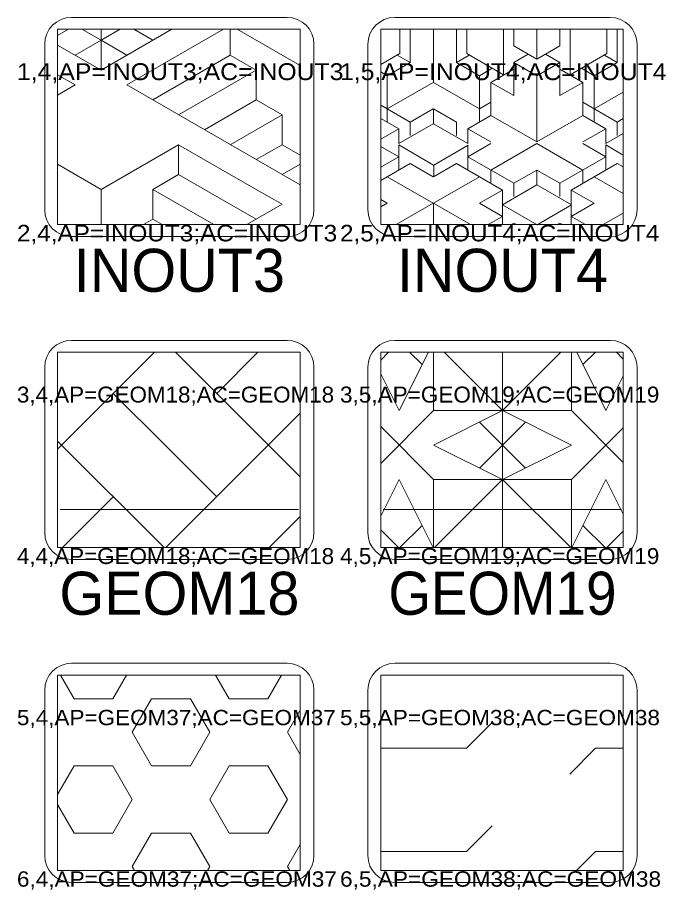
# Model space of a CAD drawing. Extents: x 95935 to 95946.4, y 95971.2 to 95974.7.
# Drawn here: x 95936.835 to 95938.031, y 95973.111 to 95974.732 of the extents above; entities that cross this region are included whole.
import ezdxf
from ezdxf.enums import TextEntityAlignment as Align

# ---------------------------------------------------------------- set-up
doc = ezdxf.new("R2010")
doc.units = 0
doc.header["$LTSCALE"] = 0.032
for name, color, linetype, lineweight in [('1', 7, 'Continuous', 13), ('2', 7, 'Continuous', 13), ('25', 7, 'Continuous', 13), ('6', 7, 'Continuous', 13), ('63', 7, 'Continuous', 13)]:
    doc.layers.add(name, color=color, linetype=linetype, lineweight=lineweight)
doc.layers.add('20', color=7, linetype='Continuous')

msp = doc.modelspace()

# ---------------------------------------------------------------- linework, layer by layer
at = {"layer": '1'}
for p, q in [((95936.9357, 95974.7318), (95937.3357, 95974.7318)), ((95937.5357, 95974.7318), (95937.9357, 95974.7318)), ((95936.8857, 95974.3747), (95936.8857, 95974.6818)), ((95937.3857, 95974.6818), (95937.3857, 95974.3747)), ((95937.4857, 95974.3747), (95937.4857, 95974.6818)), ((95937.9857, 95974.6818), (95937.9857, 95974.3747)), ((95937.3357, 95974.3247), (95936.9357, 95974.3247)), ((95937.9357, 95974.3247), (95937.5357, 95974.3247)), ((95936.9357, 95974.1318), (95937.3357, 95974.1318)), ((95937.5357, 95974.1318), (95937.9357, 95974.1318)), ((95936.8857, 95973.7747), (95936.8857, 95974.0818)), ((95937.3857, 95974.0818), (95937.3857, 95973.7747)), ((95937.4857, 95973.7747), (95937.4857, 95974.0818)), ((95937.9857, 95974.0818), (95937.9857, 95973.7747)), ((95937.3357, 95973.7247), (95936.9357, 95973.7247)), ((95937.9357, 95973.7247), (95937.5357, 95973.7247)), ((95936.9357, 95973.5318), (95937.3357, 95973.5318)), ((95937.5357, 95973.5318), (95937.9357, 95973.5318)), ((95936.8857, 95973.1747), (95936.8857, 95973.4818)), ((95937.3857, 95973.4818), (95937.3857, 95973.1747)), ((95937.4857, 95973.1747), (95937.4857, 95973.4818)), ((95937.9857, 95973.4818), (95937.9857, 95973.1747)), ((95937.3357, 95973.1247), (95936.9357, 95973.1247)), ((95937.9357, 95973.1247), (95937.5357, 95973.1247))]:
    msp.add_line(p, q, dxfattribs=at)
for centre, start, end in [((95936.9357, 95974.6818), 90, 180), ((95937.3357, 95974.6818), 0, 90), ((95937.5357, 95974.6818), 90, 180), ((95937.9357, 95974.6818), 0, 90), ((95936.9357, 95974.3747), 180, 270), ((95937.3357, 95974.3747), 270, 0), ((95937.5357, 95974.3747), 180, 270), ((95937.9357, 95974.3747), 270, 0), ((95936.9357, 95974.0818), 90, 180), ((95937.3357, 95974.0818), 0, 90), ((95937.5357, 95974.0818), 90, 180), ((95937.9357, 95974.0818), 0, 90), ((95936.9357, 95973.7747), 180, 270), ((95937.3357, 95973.7747), 270, 0), ((95937.5357, 95973.7747), 180, 270), ((95937.9357, 95973.7747), 270, 0), ((95936.9357, 95973.4818), 90, 180), ((95937.3357, 95973.4818), 0, 90), ((95937.5357, 95973.4818), 90, 180), ((95937.9357, 95973.4818), 0, 90), ((95936.9357, 95973.1747), 180, 270), ((95937.3357, 95973.1747), 270, 0), ((95937.5357, 95973.1747), 180, 270), ((95937.9357, 95973.1747), 270, 0)]:
    msp.add_arc(centre, 0.05, start, end, dxfattribs=at)
at = {"layer": '2'}
for points in [[(95937.3601, 95974.7099), (95936.9097, 95974.7099), (95936.9097, 95974.3468), (95937.3601, 95974.3468)], [(95937.9601, 95974.7099), (95937.5097, 95974.7099), (95937.5097, 95974.3468), (95937.9601, 95974.3468)], [(95937.3601, 95974.1099), (95936.9097, 95974.1099), (95936.9097, 95973.7468), (95937.3601, 95973.7468)], [(95937.9601, 95974.1099), (95937.5097, 95974.1099), (95937.5097, 95973.7468), (95937.9601, 95973.7468)], [(95937.3601, 95973.5099), (95936.9097, 95973.5099), (95936.9097, 95973.1468), (95937.3601, 95973.1468)], [(95937.9601, 95973.5099), (95937.5097, 95973.5099), (95937.5097, 95973.1468), (95937.9601, 95973.1468)]]:
    msp.add_lwpolyline(points, close=True, dxfattribs=at)
at = {"layer": '25'}
for p, q in [((95937.3569, 95973.8178), (95936.9141, 95973.8178)), ((95937.9569, 95973.8178), (95937.5141, 95973.8178))]:
    msp.add_line(p, q, dxfattribs=at)
at = {"layer": '6'}
for p, q in [((95936.9097, 95974.6982), (95936.9299, 95974.7099)), ((95936.9549, 95974.7099), (95936.9904, 95974.6894)), ((95936.9904, 95974.634), (95937.1219, 95974.7099)), ((95936.9904, 95974.6894), (95937.0259, 95974.7099)), ((95936.9904, 95974.634), (95936.9904, 95974.7099)), ((95937.0384, 95974.6063), (95937.2179, 95974.7099)), ((95937.0509, 95974.7099), (95937.0864, 95974.6894)), ((95937.2304, 95974.6617), (95937.2304, 95974.7099)), ((95937.2429, 95974.7099), (95937.3601, 95974.6423)), ((95937.5453, 95974.6647), (95937.5453, 95974.7099)), ((95937.5644, 95974.6482), (95937.5644, 95974.7098)), ((95937.6076, 95974.6112), (95937.6076, 95974.7099)), ((95937.6503, 95974.6482), (95937.6503, 95974.7098)), ((95937.6694, 95974.6647), (95937.6694, 95974.7099)), ((95937.7379, 95974.6252), (95937.7379, 95974.7099)), ((95937.757, 95974.7099), (95937.757, 95974.679)), ((95937.7996, 95974.7099), (95937.7996, 95974.6544)), ((95937.8423, 95974.7099), (95937.8423, 95974.679)), ((95937.8614, 95974.6252), (95937.8614, 95974.7099)), ((95937.9298, 95974.6647), (95937.9298, 95974.7099)), ((95937.9489, 95974.6482), (95937.9489, 95974.7098)), ((95936.9424, 95974.6617), (95936.9904, 95974.6894)), ((95936.9904, 95974.6894), (95937.0384, 95974.6617)), ((95936.9097, 95974.6806), (95936.9904, 95974.634)), ((95937.7996, 95974.6544), (95937.757, 95974.679)), ((95937.7996, 95974.6544), (95937.8423, 95974.679)), ((95937.0864, 95974.5786), (95937.2304, 95974.6617)), ((95937.2784, 95974.634), (95937.2304, 95974.6617)), ((95937.5097, 95974.6442), (95937.5453, 95974.6647)), ((95937.5644, 95974.6482), (95937.5405, 95974.662)), ((95937.6503, 95974.6482), (95937.6742, 95974.662)), ((95937.7379, 95974.6252), (95937.6694, 95974.6647)), ((95937.757, 95974.6482), (95937.7836, 95974.6636)), ((95937.8423, 95974.6482), (95937.8156, 95974.6636)), ((95937.8614, 95974.6252), (95937.9298, 95974.6647)), ((95937.9489, 95974.6482), (95937.9251, 95974.662)), ((95937.1344, 95974.5509), (95937.2784, 95974.634)), ((95937.5644, 95974.6482), (95937.5217, 95974.6236)), ((95937.6503, 95974.6482), (95937.693, 95974.6236)), ((95937.693, 95974.6236), (95937.7168, 95974.6373)), ((95937.7143, 95974.6112), (95937.757, 95974.6359)), ((95937.757, 95974.5866), (95937.757, 95974.6482)), ((95937.7996, 95974.6236), (95937.757, 95974.6482)), ((95937.7996, 95974.6236), (95937.8423, 95974.6482)), ((95937.8423, 95974.5866), (95937.8423, 95974.6482)), ((95937.8849, 95974.6112), (95937.8423, 95974.6359)), ((95937.9063, 95974.6236), (95937.8824, 95974.6373)), ((95937.9489, 95974.6482), (95937.9063, 95974.6236)), ((95936.9097, 95974.6252), (95936.9424, 95974.6063)), ((95937.5217, 95974.6236), (95937.5097, 95974.6305)), ((95937.5217, 95974.562), (95937.5217, 95974.6236)), ((95937.693, 95974.562), (95937.693, 95974.6236)), ((95937.7996, 95974.5004), (95937.7996, 95974.6236)), ((95937.9063, 95974.562), (95937.9063, 95974.6236)), ((95936.9097, 95974.5874), (95936.9424, 95974.6063)), ((95937.0384, 95974.6063), (95937.3601, 95974.4206)), ((95937.6071, 95974.6112), (95937.5217, 95974.562)), ((95937.6076, 95974.6112), (95937.693, 95974.562)), ((95937.7143, 95974.5497), (95937.7143, 95974.6112)), ((95937.757, 95974.5866), (95937.7143, 95974.6112)), ((95937.8423, 95974.5866), (95937.8849, 95974.6112)), ((95937.8849, 95974.5497), (95937.8849, 95974.6112)), ((95937.9601, 95974.593), (95937.9063, 95974.562)), ((95937.1824, 95974.5232), (95937.2784, 95974.5786)), ((95937.5097, 95974.5689), (95937.5644, 95974.5373)), ((95937.693, 95974.562), (95937.7143, 95974.5743)), ((95937.8849, 95974.5743), (95937.9489, 95974.5373)), ((95937.5217, 95974.562), (95937.5217, 95974.5373)), ((95937.5644, 95974.5373), (95937.6071, 95974.562)), ((95937.6076, 95974.562), (95937.6503, 95974.5374)), ((95937.6076, 95974.562), (95937.6076, 95974.5344)), ((95937.693, 95974.562), (95937.693, 95974.5374)), ((95937.9063, 95974.562), (95937.9063, 95974.5373)), ((95937.2304, 95974.4954), (95937.3264, 95974.5509)), ((95937.3264, 95974.4954), (95937.3264, 95974.5509)), ((95937.5097, 95974.5443), (95937.5431, 95974.525)), ((95937.5644, 95974.5373), (95937.5644, 95974.5127)), ((95937.6503, 95974.5374), (95937.6503, 95974.5127)), ((95937.6716, 95974.525), (95937.7143, 95974.5497)), ((95937.7996, 95974.5004), (95937.7143, 95974.5497)), ((95937.7996, 95974.5004), (95937.8849, 95974.5497)), ((95937.885, 95974.5497), (95937.9276, 95974.525)), ((95937.9489, 95974.5373), (95937.9601, 95974.5438)), ((95937.9489, 95974.5373), (95937.9489, 95974.5127)), ((95937.5097, 95974.5058), (95937.5431, 95974.525)), ((95937.5431, 95974.525), (95937.5431, 95974.4976)), ((95937.5434, 95974.4976), (95937.6071, 95974.5344)), ((95937.6076, 95974.5344), (95937.6716, 95974.4975)), ((95937.6716, 95974.525), (95937.7143, 95974.5004)), ((95937.6716, 95974.525), (95937.6716, 95974.4975)), ((95937.8849, 95974.5004), (95937.9276, 95974.525)), ((95937.9276, 95974.525), (95937.9276, 95974.4976)), ((95937.9279, 95974.4976), (95937.9601, 95974.5162)), ((95936.9904, 95974.4123), (95937.1344, 95974.4954)), ((95937.1344, 95974.4954), (95937.2784, 95974.4123)), ((95937.1344, 95974.44), (95937.1344, 95974.4954)), ((95937.2784, 95974.4677), (95937.3264, 95974.4954)), ((95937.3264, 95974.4954), (95937.3601, 95974.476)), ((95937.5097, 95974.492), (95937.5431, 95974.4728)), ((95937.5431, 95974.4949), (95937.6076, 95974.4576)), ((95937.5431, 95974.4482), (95937.5431, 95974.4949)), ((95937.6082, 95974.4576), (95937.6719, 95974.4944)), ((95937.6716, 95974.4728), (95937.7143, 95974.4975)), ((95937.6716, 95974.4482), (95937.6716, 95974.4944)), ((95937.7143, 95974.4482), (95937.7996, 95974.4975)), ((95937.7996, 95974.4975), (95937.8849, 95974.4482)), ((95937.8849, 95974.4974), (95937.9276, 95974.4728)), ((95937.9276, 95974.4482), (95937.9276, 95974.4949)), ((95937.9276, 95974.4949), (95937.9601, 95974.4761)), ((95937.5097, 95974.4536), (95937.5431, 95974.4728)), ((95937.6716, 95974.4728), (95937.7569, 95974.4236)), ((95937.6716, 95974.4728), (95937.6716, 95974.4482)), ((95937.8423, 95974.4236), (95937.9276, 95974.4728)), ((95936.9097, 95974.4589), (95936.9904, 95974.4123)), ((95937.3264, 95974.44), (95937.3601, 95974.4594)), ((95937.5097, 95974.4289), (95937.5644, 95974.4605)), ((95937.5644, 95974.4605), (95937.6071, 95974.4359)), ((95937.6076, 95974.4359), (95937.6503, 95974.4605)), ((95937.6082, 95974.4576), (95937.6082, 95974.4362)), ((95937.6503, 95974.4605), (95937.7356, 95974.4112)), ((95937.8636, 95974.4112), (95937.9489, 95974.4605)), ((95937.9489, 95974.4605), (95937.9601, 95974.454)), ((95937.0864, 95974.4123), (95937.1344, 95974.44)), ((95937.1344, 95974.44), (95937.1824, 95974.4123)), ((95937.7143, 95974.4482), (95937.7143, 95974.4236)), ((95937.7996, 95974.4482), (95937.7996, 95974.4206)), ((95937.8849, 95974.4482), (95937.8849, 95974.4236)), ((95937.6071, 95974.3866), (95937.5217, 95974.4359)), ((95937.6076, 95974.3866), (95937.693, 95974.4359)), ((95937.7569, 95974.4236), (95937.7569, 95974.3989)), ((95937.8423, 95974.4236), (95937.8423, 95974.3989)), ((95937.9601, 95974.4048), (95937.9063, 95974.4359)), ((95936.9904, 95974.3468), (95936.9904, 95974.4123)), ((95937.0864, 95974.3569), (95937.0864, 95974.4123)), ((95937.0864, 95974.4123), (95937.1999, 95974.3468)), ((95937.1824, 95974.4123), (95937.2784, 95974.3569)), ((95937.2784, 95974.4123), (95937.3264, 95974.3846)), ((95937.693, 95974.3866), (95937.7356, 95974.4112)), ((95937.7356, 95974.4112), (95937.7356, 95974.3468)), ((95937.7359, 95974.3838), (95937.7996, 95974.4206)), ((95937.7996, 95974.4206), (95937.8639, 95974.3835)), ((95937.8636, 95974.4112), (95937.9063, 95974.3866)), ((95937.8636, 95974.4112), (95937.8636, 95974.3468)), ((95937.5097, 95974.3935), (95937.5217, 95974.3866)), ((95937.2609, 95974.3468), (95937.3264, 95974.3846)), ((95937.5097, 95974.3797), (95937.5217, 95974.3866)), ((95937.6071, 95974.3866), (95937.5382, 95974.3468)), ((95937.6076, 95974.3866), (95937.6765, 95974.3468)), ((95937.6076, 95974.3866), (95937.6076, 95974.3468)), ((95937.693, 95974.3866), (95937.7356, 95974.362)), ((95937.7359, 95974.3838), (95937.8002, 95974.3467)), ((95937.8002, 95974.3467), (95937.8639, 95974.3835)), ((95937.8636, 95974.362), (95937.9063, 95974.3866)), ((95937.7094, 95974.3468), (95937.7356, 95974.362)), ((95937.8636, 95974.362), (95937.8899, 95974.3468)), ((95937.8636, 95974.362), (95937.8636, 95974.3468)), ((95937.9601, 95974.3684), (95937.9227, 95974.3468)), ((95936.9119, 95974.3468), (95936.9097, 95974.3481)), ((95937.0689, 95974.3468), (95937.0864, 95974.3569)), ((95937.0864, 95974.3569), (95937.1039, 95974.3468)), ((95937.7519, 95974.3468), (95937.7569, 95974.3497)), ((95937.7569, 95974.3497), (95937.7619, 95974.3468)), ((95937.8373, 95974.3468), (95937.8423, 95974.3497)), ((95937.8423, 95974.3497), (95937.8473, 95974.3468)), ((95937.0896, 95974.1099), (95936.9097, 95973.93)), ((95937.1286, 95974.1099), (95937.3601, 95973.8784)), ((95937.2816, 95974.1099), (95937.2051, 95974.0334)), ((95937.5244, 95974.1099), (95937.5097, 95974.0952)), ((95937.5634, 95974.1099), (95937.5866, 95974.0867)), ((95937.6079, 95974.1099), (95937.6079, 95974.0014)), ((95937.7359, 95974.0014), (95937.6274, 95974.1099)), ((95937.7359, 95974.1099), (95937.7359, 95973.7468)), ((95937.7359, 95974.0014), (95937.8444, 95974.1099)), ((95937.8639, 95974.1099), (95937.8639, 95974.0014)), ((95937.9084, 95974.1099), (95937.8852, 95974.0867)), ((95937.9474, 95974.1099), (95937.9601, 95974.0972)), ((95937.1091, 95973.9374), (95937.0131, 95974.0334)), ((95937.5097, 95973.9032), (95937.6079, 95974.0014)), ((95937.6079, 95974.0014), (95937.7359, 95974.0014)), ((95937.8639, 95974.0014), (95937.7359, 95974.0014)), ((95937.8639, 95974.0014), (95937.9601, 95973.9052)), ((95937.3601, 95973.9964), (95937.1105, 95973.7468)), ((95937.5097, 95973.9716), (95937.6079, 95973.8734)), ((95937.7359, 95973.9374), (95937.6932, 95973.9801)), ((95937.7359, 95973.9374), (95937.7786, 95973.9801)), ((95937.8639, 95973.8734), (95937.9601, 95973.9696)), ((95936.9097, 95973.9448), (95937.1077, 95973.7468)), ((95937.1091, 95973.9374), (95937.2051, 95973.8414)), ((95937.7359, 95973.9374), (95937.6932, 95973.8947)), ((95937.7359, 95973.9374), (95937.7786, 95973.8947)), ((95937.6079, 95973.8734), (95937.7359, 95973.8734)), ((95937.6079, 95973.7468), (95937.6079, 95973.8734)), ((95937.7359, 95973.8734), (95937.6093, 95973.7468)), ((95937.7359, 95973.8734), (95937.8625, 95973.7468)), ((95937.8639, 95973.7468), (95937.8639, 95973.8734)), ((95936.9185, 95973.7468), (95937.0131, 95973.8414)), ((95937.3025, 95973.7468), (95937.3601, 95973.8044)), ((95937.5425, 95973.7468), (95937.5097, 95973.7796)), ((95937.5453, 95973.7468), (95937.5866, 95973.7881)), ((95937.9265, 95973.7468), (95937.8852, 95973.7881)), ((95937.9293, 95973.7468), (95937.9601, 95973.7776)), ((95936.9403, 95973.466), (95936.9149, 95973.5099)), ((95937.0377, 95973.5099), (95937.0123, 95973.466)), ((95937.2283, 95973.466), (95937.2029, 95973.5099)), ((95937.3257, 95973.5099), (95937.3003, 95973.466)), ((95936.9403, 95973.466), (95937.0123, 95973.466)), ((95937.0843, 95973.466), (95937.0483, 95973.4036)), ((95937.0843, 95973.466), (95937.1563, 95973.466)), ((95937.1923, 95973.4036), (95937.1563, 95973.466)), ((95937.2283, 95973.466), (95937.3003, 95973.466)), ((95937.3601, 95973.4449), (95937.3363, 95973.4036)), ((95937.6688, 95973.3741), (95937.7168, 95973.4221)), ((95937.0843, 95973.3413), (95937.0483, 95973.4036)), ((95937.1923, 95973.4036), (95937.1563, 95973.3413)), ((95937.3601, 95973.3624), (95937.3363, 95973.4036)), ((95937.5097, 95973.3741), (95937.6688, 95973.3741)), ((95937.8608, 95973.3261), (95937.9088, 95973.3741)), ((95937.9088, 95973.3741), (95937.9601, 95973.3741)), ((95936.9403, 95973.3413), (95936.9097, 95973.2883)), ((95936.9403, 95973.3413), (95937.0123, 95973.3413)), ((95937.0483, 95973.2789), (95937.0123, 95973.3413)), ((95937.0843, 95973.3413), (95937.1563, 95973.3413)), ((95937.2283, 95973.3413), (95937.1923, 95973.2789)), ((95937.2283, 95973.3413), (95937.3003, 95973.3413)), ((95937.3363, 95973.2789), (95937.3003, 95973.3413)), ((95937.0483, 95973.2789), (95937.0123, 95973.2165)), ((95937.2283, 95973.2165), (95937.1923, 95973.2789)), ((95937.3363, 95973.2789), (95937.3003, 95973.2165)), ((95936.9403, 95973.2165), (95936.9097, 95973.2695)), ((95937.6688, 95973.1821), (95937.7168, 95973.2301)), ((95936.9403, 95973.2165), (95937.0123, 95973.2165)), ((95937.0843, 95973.2165), (95937.0483, 95973.1542)), ((95937.0843, 95973.2165), (95937.1563, 95973.2165)), ((95937.1923, 95973.1542), (95937.1563, 95973.2165)), ((95937.2283, 95973.2165), (95937.3003, 95973.2165)), ((95937.3601, 95973.1954), (95937.3363, 95973.1542)), ((95937.5097, 95973.1821), (95937.6688, 95973.1821)), ((95937.8735, 95973.1468), (95937.9088, 95973.1821)), ((95937.9088, 95973.1821), (95937.9601, 95973.1821)), ((95937.0526, 95973.1468), (95937.0483, 95973.1542)), ((95937.1923, 95973.1542), (95937.188, 95973.1468)), ((95937.3406, 95973.1468), (95937.3363, 95973.1542))]:
    msp.add_line(p, q, dxfattribs=at)
for points in [[(95937.3264, 95974.5509), (95937.2784, 95974.5786), (95937.2784, 95974.634)], [(95937.7569, 95974.4236), (95937.7996, 95974.4482), (95937.8423, 95974.4236)], [(95937.5097, 95974.0698), (95937.5439, 95974.0014), (95937.5982, 95974.1099)], [(95937.8737, 95974.1099), (95937.9279, 95974.0014), (95937.9601, 95974.0658)], [(95937.7359, 95974.0014), (95937.6079, 95973.9374), (95937.7359, 95973.8734)], [(95937.8639, 95973.8734), (95937.7359, 95973.8734), (95937.8639, 95973.9374), (95937.7359, 95974.0014)], [(95937.6072, 95973.7468), (95937.5439, 95973.8734), (95937.5097, 95973.805)], [(95937.9601, 95973.809), (95937.9279, 95973.8734), (95937.8646, 95973.7468)]]:
    msp.add_lwpolyline(points, dxfattribs=at)

# ---------------------------------------------------------------- texts
at = {"layer": '20'}
for s, p in [('INOUT3', (95937.1358, 95974.222)), ('INOUT4', (95937.7358, 95974.222)), ('GEOM18', (95937.1358, 95973.622))]:
    msp.add_text(s, height=0.08, dxfattribs=at).set_placement(p, align=Align.CENTER)
at = {"layer": '20', "width": 0.95}
msp.add_text('GEOM19', height=0.08, dxfattribs=at).set_placement((95937.7358, 95973.622), align=Align.CENTER)
at = {"layer": '63'}
for s, height, width, p in [('1,4,AP=INOUT3;AC=INOUT3', 0.0313, 1.1, (95936.8341, 95974.6154)), ('1,5,AP=INOUT4;AC=INOUT4', 0.0313, 1.1, (95937.4341, 95974.6154)), ('2,4,AP=INOUT3;AC=INOUT3', 0.0307, 1.1, (95936.8341, 95974.3157)), ('2,5,AP=INOUT4;AC=INOUT4', 0.0306, 1.1, (95937.4341, 95974.3158)), ('3,4,AP=GEOM18;AC=GEOM18', 0.0296, 1.05, (95936.8341, 95974.0163)), ('3,5,AP=GEOM19;AC=GEOM19', 0.0298, 1.05, (95937.4341, 95974.0162)), ('4,4,AP=GEOM18;AC=GEOM18', 0.0296, 1.05, (95936.8341, 95973.7163)), ('4,5,AP=GEOM19;AC=GEOM19', 0.0298, 1.05, (95937.4341, 95973.7162)), ('5,4,AP=GEOM37;AC=GEOM37', 0.0284, 1.1, (95936.8341, 95973.4169)), ('5,5,AP=GEOM38;AC=GEOM38', 0.0285, 1.1, (95937.4341, 95973.4168)), ('6,4,AP=GEOM37;AC=GEOM37', 0.0285, 1.1, (95936.8341, 95973.1168)), ('6,5,AP=GEOM38;AC=GEOM38', 0.0286, 1.1, (95937.4341, 95973.1168))]:
    msp.add_text(s, height=height, dxfattribs=dict(at, width=width)).set_placement(p)

doc.saveas('drawing.dxf')
